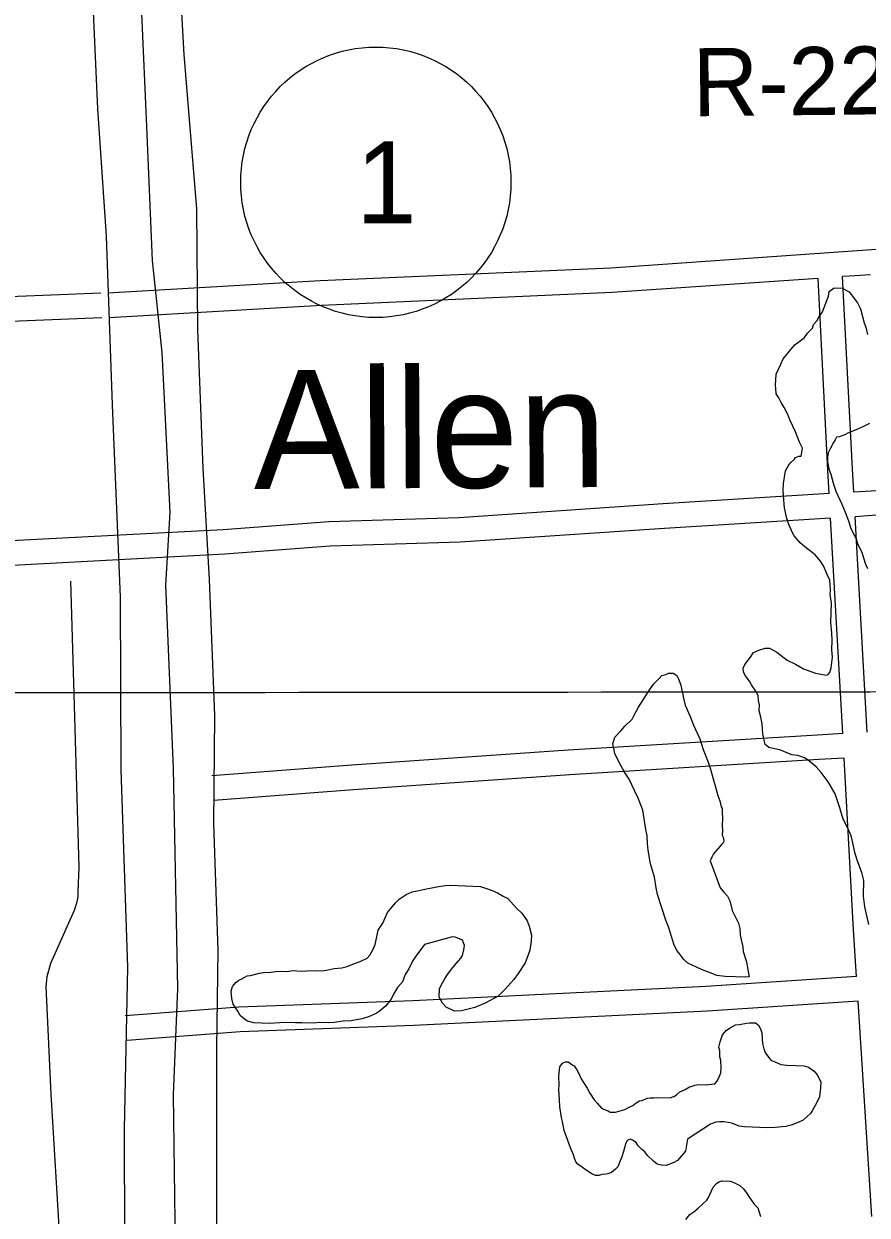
# Model space of a CAD drawing. Extents: x 3297716 to 3335574, y 688621 to 713991.
# Drawn here: x 3319475 to 3320505, y 708530 to 709984 of the extents above; entities that cross this region are included whole.
import ezdxf

# ---------------------------------------------------------------- set-up
doc = ezdxf.new("R2010")
doc.units = 0
for name, color, linetype in [('V-GRID-MAJR', 7, 'Continuous'), ('V-RIVR-RANG-IDEN', 7, 'Continuous'), ('V-ROAD-CNTR', 7, 'Continuous'), ('V-ROAD-IDEN', 7, 'Continuous'), ('V-SITE-VEGE', 7, 'Continuous'), ('V-TOPO-GNAM-IDEN', 7, 'Continuous'), ('V-TOPO-SHOR', 7, 'Continuous')]:
    doc.layers.add(name, color=color, linetype=linetype)

msp = doc.modelspace()

# ---------------------------------------------------------------- linework, layer by layer
at = {"layer": 'V-GRID-MAJR'}
msp.add_spline([(3301840.245, 709153.404), (3307091.973, 709156.841), (3312343.699, 709161.042), (3317595.4250000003, 709166.008), (3322847.151, 709171.736), (3328098.875, 709178.229), (3333350.598, 709185.486), (3333350.599, 709185.486)], degree=3, dxfattribs=at)
at = {"layer": 'V-ROAD-CNTR'}
for points in [[(3319423.187116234, 712204.995563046), (3319431.096100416, 712024.550923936), (3319452.263058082, 711723.9585251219), (3319471.097020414, 711433.8411053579), (3319475.9230107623, 711304.9763630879), (3319509.501943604, 710784.1184048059), (3319529.986902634, 710456.003061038), (3319546.2848700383, 710208.866555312), (3319558.347845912, 710026.2349205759), (3319565.1948322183, 709880.1402127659), (3319575.68881123, 709725.1335227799), (3319582.800797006, 709519.154934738), (3319592.9267767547, 709284.443404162), (3319593.4297757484, 709073.6478257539), (3319601.5927594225, 708833.1713067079), (3319597.705767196, 708635.5307019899), (3319598.4727656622, 708364.8492433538), (3319604.881752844, 708160.1196528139), (3319612.5447375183, 707938.551095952), (3319623.37871585, 707776.608419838), (3319639.210684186, 707384.1952046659)], [(3319480.960000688, 712205.0545629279), (3319484.104994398, 712134.43370417), (3319486.461989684, 712036.2519005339), (3319512.837936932, 711766.827439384), (3319527.815906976, 711448.497076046), (3319527.447907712, 711327.3993182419), (3319550.9018608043, 711036.8668993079), (3319567.824826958, 710785.69640165), (3319575.8088109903, 710627.357718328), (3319594.37877385, 710397.1251787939), (3319598.961764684, 710294.9883830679), (3319616.416729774, 710052.614867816), (3319624.8527129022, 709858.8942552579), (3319631.704699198, 709695.2595825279), (3319643.5136755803, 709583.2088066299), (3319653.185656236, 709388.2651965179), (3319647.92866675, 709299.22937459), (3319657.4136477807, 709075.3968222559), (3319662.5526375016, 708807.1763586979), (3319657.4756476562, 708677.3976182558), (3319662.422637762, 708306.2703605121), (3319668.6516253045, 707954.7810634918), (3319671.591619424, 707777.1554187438), (3319694.104574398, 707409.8861532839)], [(3319710.995540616, 708252.0204690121), (3319710.850540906, 708734.031504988), (3319712.24853811, 708853.79026547), (3319706.9335487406, 709007.8739573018), (3319708.3535459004, 709140.2546925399), (3319701.721559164, 709305.933361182), (3319693.97857465, 709441.92908919), (3319687.72358716, 709610.8347513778), (3319686.3675898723, 709758.3744562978), (3319670.814620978, 709946.719079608), (3319663.97363466, 710070.8858312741), (3319649.7216631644, 710309.0313549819), (3319638.2716860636, 710439.9240931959), (3319622.3147179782, 710680.125612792), (3319620.4077217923, 710793.089386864), (3319604.2117541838, 711005.4689621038), (3319596.580769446, 711158.7976554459), (3319587.0767884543, 711356.851259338), (3319580.53880153, 711514.0839448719), (3319563.9378347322, 711728.1545167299), (3319553.041856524, 711880.4672121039), (3319535.345891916, 712205.1105628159)], [(3321443.3992820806, 709758.3230696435), (3321281.866398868, 709746.6474797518), (3321096.859768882, 709742.485488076), (3320717.7515271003, 709722.8145274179), (3320481.417999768, 709706.0795608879), (3320191.8785788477, 709686.101600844), (3319836.9682886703, 709670.505632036), (3319577.73880713, 709655.3216624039)], [(3320444.900072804, 709673.4886260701), (3320193.5705754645, 709656.1476607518), (3319838.5042855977, 709640.5436919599), (3319579.4928036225, 709625.3737222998)], [(3320458.614045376, 709410.8181514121), (3320457.0040485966, 709439.6140938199), (3320444.900072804, 709673.4886260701)], [(3320509.168944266, 709677.9696171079), (3320483.509995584, 709676.1536207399), (3320474.833012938, 709675.554621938)], [(3320488.557985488, 709412.6661477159), (3320486.9599886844, 709441.2260905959), (3320474.833012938, 709675.554621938)], [(3319569.285824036, 709655.444662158), (3319285.622391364, 709643.8806852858), (3318862.7912370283, 709618.6397357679), (3318368.584225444, 709593.5347859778), (3318317.4293277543, 709589.791793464)], [(3319570.5078215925, 709625.46872211), (3319287.126388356, 709613.916745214), (3318864.44523372, 709588.685795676), (3318370.440221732, 709563.590845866), (3318297.9263667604, 709558.284856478)], [(3320458.615045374, 709410.8191514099), (3320255.615451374, 709398.2921764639), (3320006.275950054, 709381.462210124), (3319847.512267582, 709376.562219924), (3319718.512525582, 709366.80423944), (3319467.3710278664, 709353.6272657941), (3319292.3463779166, 709345.3602823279), (3318881.8851988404, 709317.1973386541), (3318332.93629674, 709288.2313965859), (3318306.5723494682, 709287.3563983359)], [(3320520.987920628, 709414.44914415), (3320509.6019434, 709413.9651451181), (3320488.557985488, 709412.667147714)], [(3320460.291042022, 709380.865211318), (3320257.549447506, 709368.3542363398), (3320007.7499471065, 709351.4942700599), (3319849.106264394, 709346.5962798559), (3319720.430521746, 709336.86429932), (3319468.865024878, 709323.6653257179), (3319378.446205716, 709319.393334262)], [(3320474.9930126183, 709117.983737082), (3320460.290042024, 709380.865211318)], [(3320504.9419527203, 709119.7347335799), (3320490.232982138, 709382.7132076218)], [(3320522.648917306, 709384.493204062), (3320511.16194028, 709384.0052050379), (3320490.233982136, 709382.7132076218)], [(3320474.994012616, 709117.9847370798), (3320444.0940744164, 709116.1787406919), (3320139.971682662, 709097.726777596), (3319875.4932116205, 709079.3988142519), (3319704.834552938, 709066.4238402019)], [(3320476.6700092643, 709088.0317969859), (3320445.878070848, 709086.2328005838), (3320141.91767877, 709067.788837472), (3319877.6672072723, 709049.476874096), (3319707.1085483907, 709036.5099000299)], [(3320491.98197864, 708821.4823300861), (3320488.372985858, 708878.7742155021), (3320476.669009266, 709088.030796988)], [(3320491.9829786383, 708821.4823300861), (3320308.1533462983, 708809.3763542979), (3319950.0570624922, 708791.912389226), (3319737.587487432, 708784.2704045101), (3319598.985764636, 708773.6824256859)], [(3320493.868974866, 708791.5413899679), (3320309.869342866, 708779.424414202), (3319951.327059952, 708761.9384491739), (3319739.269484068, 708754.312464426), (3319601.271760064, 708743.7704855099)], [(3320510.414941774, 708528.8699153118), (3320493.867974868, 708791.5413899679)]]:
    msp.add_lwpolyline(points, dxfattribs=at)
at = {"layer": 'V-ROAD-IDEN'}
msp.add_circle((3319904.919947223, 709790.7016260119), 165.00000000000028, dxfattribs=at)
msp.add_circle((3319904.919947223, 709790.7016260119), 165.00000000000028, dxfattribs=at)
at = {"layer": 'V-SITE-VEGE'}
for points in [[(3320460.041, 709293.952), (3320459.177, 709305.04), (3320456.2120000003, 709312.308), (3320451.423, 709322.899), (3320447.733, 709328.246), (3320441.548, 709336.29), (3320428.92, 709345.889), (3320423.255, 709350.6630000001), (3320415.794, 709359.408), (3320413.949, 709362.081), (3320409.187, 709373.322), (3320406.8710000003, 709380.564), (3320404.1350000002, 709393.677), (3320403.193, 709402.816), (3320402.353, 709414.5530000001), (3320402.685, 709422.993), (3320405.2430000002, 709438.498), (3320409.443, 709446.137), (3320412.167, 709449.281), (3320416.216, 709453.022), (3320417.59, 709454.919), (3320421.563, 709456.715), (3320424.1580000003, 709456.612), (3320425.838, 709466.3), (3320422.225, 709473.5920000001), (3320417.515, 709486.132), (3320410.285, 709500.72), (3320407.9420000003, 709507.3150000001), (3320403.7290000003, 709515.933), (3320400.0640000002, 709521.927), (3320397.0470000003, 709527.897), (3320393.9790000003, 709532.571), (3320393.5840000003, 709539.088), (3320393.086, 709543.009), (3320393.623, 709556.643), (3320399.3000000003, 709568.773), (3320402.15, 709575.1630000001), (3320408.301, 709582.724), (3320411.698, 709586.493), (3320417.148, 709592.782), (3320419.821, 709594.627), (3320428.541, 709601.439), (3320431.99, 709606.504), (3320438.0870000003, 709612.7660000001), (3320439.563, 709617.26), (3320443.639, 709621.653), (3320446.438, 709626.7440000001), (3320450.563, 709632.433), (3320457.819, 709651.656), (3320458.698, 709657.4720000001), (3320464.719, 709661.789), (3320474.457, 709661.406), (3320482.7430000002, 709657.179), (3320493.27, 709643.763), (3320496.887, 709636.47), (3320501.417, 709619.385), (3320503.162, 709614.116), (3320505.4020000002, 709604.925)], [(3320507.6410000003, 709496.252), (3320500.348, 709492.637), (3320493.078, 709489.669), (3320480.5130000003, 709484.312), (3320477.84, 709482.464), (3320470.6010000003, 709480.148), (3320467.326, 709479.628), (3320465.901, 709476.431), (3320463.826, 709473.263), (3320459.623, 709465.6240000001), (3320457.473, 709460.508), (3320456.619, 709455.339), (3320456.392, 709449.496), (3320458.008, 709440.978), (3320460.3510000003, 709434.386), (3320463.787, 709422.546), (3320466.701, 709413.979), (3320473.882, 709398.093), (3320478.043, 709388.177), (3320482.18, 709377.609), (3320485.0700000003, 709368.397), (3320491.103, 709356.453), (3320493.395, 709348.562), (3320498.232, 709339.268), (3320500.573, 709332.676), (3320502.867, 709324.783), (3320505.259, 709319.487)], [(3320507.074, 708885.073), (3320502.072, 708906.7270000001), (3320500.6350000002, 708919.787), (3320500.723, 708938.6410000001), (3320498.509, 708948.479), (3320492.602, 708963.667), (3320489.713, 708972.883), (3320487.575, 708984.671), (3320485.307, 708993.212), (3320481.119, 709002.481), (3320475.711, 709013.745), (3320471.701, 709027.556), (3320469.333, 709033.502), (3320467.017, 709040.746), (3320465.87, 709044.6900000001), (3320457.342, 709059.331), (3320448.685, 709070.724), (3320442.447, 709077.47), (3320433.0160000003, 709085.644), (3320428.574, 709088.419), (3320420.234, 709091.346), (3320413.12, 709092.275), (3320398.39, 709098.055), (3320390.002, 709099.685), (3320384.859, 709101.186), (3320382.338, 709103.236), (3320380.4420000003, 709104.61), (3320377.7060000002, 709117.726), (3320376.89, 709130.108), (3320375.25, 709137.976), (3320372.9560000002, 709145.867), (3320373.237, 709153.009), (3320372.143, 709158.254), (3320371.723, 709164.121), (3320369.954, 709168.7440000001), (3320363.791, 709177.437), (3320361.375, 709182.084), (3320355.786, 709188.806), (3320354.0160000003, 709193.426), (3320353.545, 709197.995), (3320355.669, 709202.464), (3320362.52, 709211.299), (3320365.995, 709217.015), (3320372.614, 709220.005), (3320380.507, 709222.297), (3320385.699, 709222.094), (3320394.612, 709217.191), (3320407.24, 709207.594), (3320417.447, 709202.642), (3320426.982, 709197.0650000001), (3320441.736, 709191.935), (3320448.177, 709190.383), (3320455.294, 709189.455), (3320457.2660000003, 709190.0260000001), (3320459.316, 709192.547), (3320460.844, 709198.339), (3320462.65, 709211.272), (3320461.708, 709220.4130000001), (3320462.167, 709232.098), (3320461.85, 709240.563), (3320460.412, 709253.625), (3320461.356, 709277.6460000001), (3320459.787, 709287.46), (3320460.041, 709293.952)], [(3319982.126, 708796.429), (3319982.534, 708806.817), (3319984.66, 708811.286), (3319989.536, 708819.549), (3319992.311, 708823.9890000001), (3319999.159, 708832.824), (3320003.257, 708837.865), (3320008.707, 708844.154), (3320010.782, 708847.322), (3320012.361, 708854.412), (3320013.213, 708859.582), (3320010.872, 708866.174), (3320005.105, 708868.351), (3320001.9080000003, 708869.779), (3319998.664, 708869.906), (3319964.497, 708860.841), (3319954.898, 708848.213), (3319950.075, 708841.252), (3319945.123, 708831.0430000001), (3319940.947, 708824.0530000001), (3319937.345, 708815.093), (3319931.221, 708808.181), (3319926.343, 708799.917), (3319923.519, 708794.177), (3319916.67, 708785.346), (3319910.6240000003, 708780.377), (3319905.2770000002, 708776.687), (3319896.0100000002, 708772.4990000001), (3319888.119, 708770.207), (3319874.356, 708767.495), (3319865.241, 708767.202), (3319854.128, 708765.689), (3319847.611, 708765.294), (3319836.575, 708765.728), (3319828.733, 708764.735), (3319814.45, 708765.296), (3319806.6350000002, 708764.952), (3319794.3000000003, 708765.435), (3319787.134, 708765.064), (3319774.748, 708764.251), (3319755.918, 708764.991), (3319748.2060000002, 708767.241), (3319745.0330000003, 708769.318), (3319739.3710000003, 708774.0920000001), (3319736.329, 708779.4130000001), (3319730.816, 708788.082), (3319729.1240000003, 708794.65), (3319728.182, 708803.79), (3319729.71, 708809.582), (3319734.457, 708814.599), (3319737.806, 708817.067), (3319741.13, 708818.888), (3319745.1010000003, 708820.68), (3319747.774, 708822.527), (3319751.693, 708823.025), (3319762.857, 708825.839), (3319770.0500000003, 708826.857), (3319773.947, 708826.703), (3319782.436, 708827.67), (3319788.303, 708828.089), (3319796.745, 708827.76), (3319803.289, 708828.802), (3319814.323, 708828.37), (3319820.842, 708828.765), (3319831.254, 708829.007), (3319839.045, 708828.702), (3319846.886, 708829.693), (3319854.1040000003, 708831.36), (3319863.2460000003, 708832.302), (3319869.8140000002, 708833.996), (3319879.054, 708837.535), (3319885.649, 708839.878), (3319894.267, 708844.093), (3319897.667, 708847.859), (3319901.84, 708854.8470000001), (3319904.017, 708860.6140000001), (3319906.348, 708870.274), (3319907.952, 708878.0160000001), (3319913.502, 708886.9), (3319919.205, 708899.681), (3319925.3540000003, 708907.243), (3319928.778, 708911.658), (3319933.503, 708916.027), (3319942.17, 708921.5380000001), (3319949.465, 708925.152), (3319956.008, 708926.197), (3319962.578, 708927.889), (3319979.607, 708931.122), (3319989.421, 708932.689), (3319995.94, 708933.082), (3320032.9450000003, 708931.63), (3320038.7120000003, 708929.453), (3320047.0500000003, 708926.527), (3320053.438, 708923.676), (3320060.427, 708919.5), (3320066.17, 708916.676), (3320076.772, 708905.205), (3320083.035, 708899.106), (3320089.822, 708889.736), (3320092.163, 708883.144), (3320094.975, 708871.978)], [(3320094.975, 708871.978), (3320094.697, 708864.839), (3320092.966, 708853.851), (3320090.738, 708846.7880000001), (3320087.16, 708838.475), (3320078.835, 708825.147), (3320073.358, 708818.21), (3320062.463, 708805.631), (3320054.343, 708797.4990000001), (3320038.403, 708789.02), (3320025.841, 708783.66), (3320009.432, 708779.753), (3320000.966, 708779.435), (3319990.758, 708784.387), (3319986.39, 708789.11), (3319982.126, 708796.429)], [(3320180.34, 708661.212), (3320182.8850000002, 708659.811), (3320188.653, 708657.636), (3320191.196, 708656.236), (3320197.69, 708655.984), (3320208.879, 708659.443), (3320213.526, 708661.862), (3320218.822, 708664.256), (3320222.844, 708667.348), (3320226.842, 708669.791), (3320230.112, 708670.314), (3320236.082, 708673.33), (3320240.002, 708673.828), (3320244.549, 708673.65), (3320247.17, 708674.197), (3320264.699, 708673.508), (3320267.347, 708674.705), (3320269.319, 708675.278), (3320272.668, 708677.748), (3320276.041, 708680.867), (3320282.662, 708683.857), (3320287.983, 708686.9), (3320289.955, 708687.4720000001), (3320294.575, 708689.241), (3320298.495, 708689.741), (3320308.235, 708689.358), (3320314.779, 708690.4), (3320318.699, 708690.8960000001), (3320321.398, 708693.393), (3320323.497, 708697.21), (3320326.3740000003, 708704.251), (3320326.6040000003, 708710.094), (3320326.311, 708719.208), (3320325.191, 708723.8030000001), (3320324.822, 708730.969), (3320323.702, 708735.5650000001), (3320325.252, 708742.006), (3320328.183, 708750.343), (3320332.957, 708756.008), (3320337.628, 708759.076), (3320344.274, 708762.7170000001), (3320348.843, 708763.188), (3320357.359, 708764.804), (3320361.281, 708765.302), (3320368.4220000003, 708765.0210000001), (3320372.215, 708762.273), (3320374.634, 708757.626), (3320376.403, 708753.004), (3320376.772, 708745.838), (3320377.191, 708739.968), (3320378.8850000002, 708733.4), (3320380.628, 708728.131), (3320386.217, 708721.407), (3320387.44, 708719.412), (3320395.128, 708716.508), (3320399.599, 708714.382), (3320406.711, 708713.453), (3320428.133, 708712.613), (3320433.278, 708711.11), (3320440.2430000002, 708706.287), (3320443.958, 708701.589), (3320448.171, 708692.971), (3320447.893, 708685.829), (3320446.809, 708674.817), (3320443.2830000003, 708667.805), (3320437.681, 708657.62), (3320435.607, 708654.4500000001), (3320426.8370000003, 708646.3420000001), (3320421.541, 708643.9500000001), (3320412.298, 708640.411), (3320405.73, 708638.715), (3320392.67, 708637.279), (3320382.9050000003, 708637.011), (3320354.989, 708638.107), (3320348.524, 708639.01), (3320339.562, 708642.612), (3320335.044, 708643.4400000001), (3320329.875, 708644.294), (3320324.681, 708644.497), (3320320.112, 708644.025), (3320315.489, 708642.256), (3320313.517, 708641.685), (3320285.486, 708623.277), (3320282.953, 708608.421), (3320273.4050000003, 708597.091), (3320268.758, 708594.675), (3320259.518, 708591.136), (3320253.6750000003, 708591.363), (3320248.5300000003, 708592.866), (3320244.115, 708596.291), (3320237.227, 708603.063), (3320233.5100000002, 708607.76), (3320229.717, 708610.51), (3320225.3510000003, 708615.233), (3320222.907, 708619.23), (3320218.463, 708622.005), (3320215.918, 708623.404), (3320211.947, 708621.61), (3320209.821, 708617.1410000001), (3320207.517, 708608.13), (3320205.313, 708601.714)], [(3320205.313, 708601.714), (3320202.438, 708594.675), (3320200.285, 708589.557), (3320197.563, 708586.4130000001), (3320192.863, 708582.696), (3320188.2430000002, 708580.927), (3320185.622, 708580.38), (3320181.0500000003, 708579.909), (3320177.1040000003, 708578.764), (3320173.211, 708578.915), (3320168.742, 708581.041), (3320161.752, 708585.219), (3320157.3370000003, 708588.6410000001), (3320151.645, 708592.764), (3320149.151, 708595.463), (3320147.381, 708600.086), (3320146.236, 708604.03), (3320142.671, 708612.621), (3320140.901, 708617.2440000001), (3320135.046, 708633.73), (3320132.884, 708644.867), (3320131.761, 708649.465), (3320129.674, 708662.55), (3320129.381, 708671.6630000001), (3320128.542, 708683.4), (3320128.798, 708689.892), (3320128.529, 708699.657), (3320128.708, 708704.204), (3320129.637, 708711.317), (3320133.062, 708715.734), (3320136.384, 708717.555), (3320139.63, 708717.4280000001), (3320145.319, 708713.3030000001), (3320147.242, 708712.576), (3320150.31, 708707.907), (3320152.7290000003, 708703.26), (3320155.721, 708696.6410000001), (3320163.077, 708685.295), (3320166.096, 708679.327), (3320171.632, 708671.307), (3320175.377, 708667.258), (3320180.34, 708661.212)], [(3320283.588, 708525.17), (3320288.386, 708531.484), (3320293.06, 708534.552), (3320298.432, 708538.8910000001), (3320309.227, 708548.871), (3320311.301, 708552.042), (3320314.875, 708560.354), (3320317.005, 708564.819), (3320321.08, 708569.214), (3320323.751, 708571.059), (3320327.697, 708572.204), (3320337.436, 708571.823), (3320341.929, 708570.3470000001), (3320349.593, 708566.795), (3320353.984, 708562.7220000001), (3320358.299, 708556.701), (3320361.369, 708552.029), (3320366.904, 708544.007), (3320371.271, 708539.287), (3320374.758, 708528.746)]]:
    msp.add_lwpolyline(points, dxfattribs=at)
msp.add_lwpolyline([(3320325.473, 708929.91), (3320329.813, 708924.5380000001), (3320334.179, 708919.8150000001), (3320337.196, 708913.843), (3320339.983, 708902.03), (3320343.6, 708894.738), (3320347.84, 708886.769), (3320349.531, 708880.201), (3320349.875, 708872.384), (3320350.944, 708866.4890000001), (3320353.2090000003, 708857.947), (3320353.629, 708852.08), (3320357.69, 708839.566), (3320358.708, 708832.3740000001), (3320360.873, 708821.237), (3320356.304, 708820.7660000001), (3320331.634, 708821.732), (3320321.271, 708822.789), (3320314.232, 708825.667), (3320302.7, 708830.0210000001), (3320296.308, 708832.872), (3320286.099, 708837.824), (3320281.085, 708842.571), (3320274.898, 708850.617), (3320272.401, 708853.3150000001), (3320268.813, 708861.259), (3320266.522, 708869.152), (3320262.485, 708882.314), (3320258.897, 708890.257), (3320249.083, 708921.851), (3320247.44, 708929.719), (3320245.3540000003, 708942.804), (3320240.148, 708959.2660000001), (3320237.536, 708975.623), (3320236.5700000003, 708984.112), (3320236.2770000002, 708993.228), (3320234.634, 709001.094), (3320231.007, 709024.644), (3320225.074, 709039.183), (3320220.886, 709048.448), (3320214.281, 709062.362), (3320208.768, 709071.031), (3320201.463, 709083.674), (3320196.65, 709093.615), (3320194.512, 709105.403), (3320196.791, 709113.765), (3320204.238, 709121.275), (3320209.012, 709126.942), (3320217.808, 709135.699), (3320219.907, 709139.519), (3320225.535, 709150.35), (3320238.683, 709170.64), (3320244.184, 709178.228), (3320250.957, 709185.115), (3320254.355, 709188.884), (3320258.95, 709190.004), (3320262.274, 709191.822), (3320268.115, 709191.593), (3320272.559, 709188.818), (3320274.353, 709184.8470000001), (3320277.294, 709176.929), (3320280.577, 709161.197), (3320282.844, 709152.654), (3320288.802, 709138.767), (3320292.9390000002, 709128.199), (3320300.74, 709111.639), (3320304.776, 709098.4770000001), (3320310.683, 709083.291), (3320313.597, 709074.724), (3320317.036, 709062.882), (3320319.301, 709054.3420000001), (3320322.737, 709042.503), (3320325.08, 709035.908), (3320326.747, 709028.691), (3320327.97, 709026.692), (3320327.74, 709020.849), (3320328.187, 709015.631), (3320327.7770000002, 709005.2440000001), (3320328.224, 709000.0210000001), (3320327.994, 708994.182), (3320329.188, 708991.534), (3320329.686, 708987.612), (3320329.586, 708985.015), (3320327.56, 708983.1460000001), (3320317.339, 708971.191), (3320315.239, 708967.3740000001), (3320313.114, 708962.905)], close=True, dxfattribs=at)
at = {"layer": 'V-TOPO-SHOR'}
msp.add_lwpolyline([(3319532.09, 709303.826), (3319536.52, 709152.3960000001), (3319542.4020000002, 708955.272), (3319541.214, 708925.331), (3319540.9560000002, 708918.8200000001), (3319539.344, 708911.06), (3319536.381, 708902.051), (3319507.738, 708837.338), (3319503.187, 708821.22), (3319502.073, 708809.528), (3319507.953, 708678.252), (3319518.983, 708495.92), (3319530.593, 708361.158), (3319547.983, 708092.515), (3319559.315, 707934.2930000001), (3319559.431, 707904.2980000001), (3319557.971, 707897.134)], dxfattribs=at)

# ---------------------------------------------------------------- texts
at = {"layer": 'V-RIVR-RANG-IDEN'}
msp.add_text('R-229.3', height=82.9999980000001, rotation=0.60223331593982, dxfattribs=at).set_placement((3320292.279, 709871.188))
at = {"layer": 'V-ROAD-IDEN'}
msp.add_text('1', height=100.00000200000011, rotation=0.058340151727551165, dxfattribs=at).set_placement((3319880.561478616, 709740.6767976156))
at = {"layer": 'V-TOPO-GNAM-IDEN'}
msp.add_text('Allen', height=144.99971199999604, rotation=0.3244054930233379, dxfattribs=at).set_placement((3319756.1094503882, 709416.4081402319))

doc.saveas('drawing.dxf')
